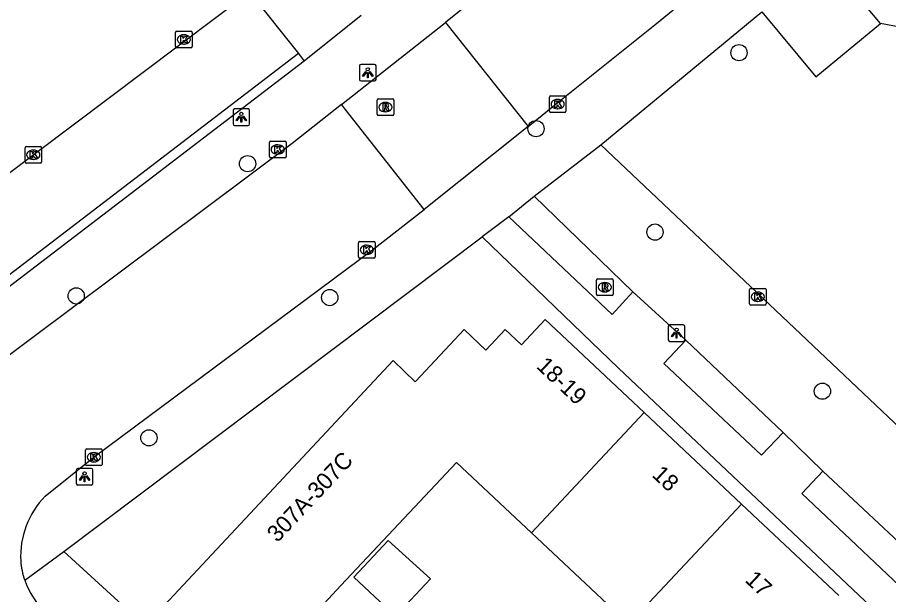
# Model space of a CAD drawing. Extents: x 159040 to 160094, y 381214 to 382518.
# Drawn here: x 159414.8 to 159467.3, y 381586.5 to 381621.3 of the extents above; entities that cross this region are included whole.
import ezdxf

# ---------------------------------------------------------------- set-up
doc = ezdxf.new("R2010")
doc.units = 0
for name, color, linetype in [('IMGEO_Boom', 7, 'Continuous'), ('IMGEO_Kolk', 7, 'Continuous'), ('IMGEO_Lichtpunt', 7, 'Continuous'), ('IMGEO_Pand', 7, 'Continuous'), ('IMGEO_Pand_nummerreeks', 7, 'Continuous'), ('IMGEO_Pand_vergunning_verleend', 7, 'Continuous'), ('IMGEO_Parkeervlak_open', 7, 'Continuous'), ('IMGEO_Rijbaan_lokaal_gesloten', 7, 'Continuous'), ('IMGEO_Rijbaan_lokaal_open', 7, 'Continuous'), ('IMGEO_Rioolput', 7, 'Continuous'), ('IMGEO_Voetpad_open', 7, 'Continuous')]:
    doc.layers.add(name, color=color, linetype=linetype)

msp = doc.modelspace()

# ---------------------------------------------------------------- linework, layer by layer
at = {"layer": 'IMGEO_Boom'}
for centre in [(159458.283, 381619.184), (159446.046, 381614.604), (159428.658, 381612.493), (159453.222, 381608.373), (159418.325, 381604.526), (159433.61, 381604.427), (159463.311, 381598.784), (159422.709, 381595.975)]:
    msp.add_circle(centre, 0.489, dxfattribs=at)
at = {"layer": 'IMGEO_Kolk'}
for p, q in [((159424.388, 381620.482), (159425.24, 381620.482)), ((159424.313, 381619.556), (159424.313, 381620.408)), ((159424.801, 381620.262), (159424.826, 381620.262)), ((159425.314, 381620.408), (159425.314, 381619.556)), ((159425.24, 381619.482), (159424.388, 381619.482)), ((159424.824, 381619.702), (159424.799, 381619.702)), ((159446.851, 381615.66), (159446.851, 381616.512)), ((159446.926, 381616.586), (159447.778, 381616.586)), ((159447.339, 381616.366), (159447.364, 381616.366)), ((159447.852, 381616.512), (159447.852, 381615.66)), ((159447.362, 381615.806), (159447.337, 381615.806)), ((159447.778, 381615.586), (159446.926, 381615.586)), ((159429.975, 381612.925), (159429.975, 381613.777)), ((159430.05, 381613.851), (159430.902, 381613.851)), ((159430.463, 381613.631), (159430.488, 381613.631)), ((159430.976, 381613.777), (159430.976, 381612.925)), ((159415.238, 381612.604), (159415.238, 381613.456)), ((159415.313, 381613.53), (159416.165, 381613.53)), ((159415.726, 381613.31), (159415.751, 381613.31)), ((159416.239, 381613.456), (159416.239, 381612.604)), ((159415.749, 381612.75), (159415.724, 381612.75)), ((159430.902, 381612.851), (159430.05, 381612.851)), ((159430.486, 381613.071), (159430.461, 381613.071)), ((159416.165, 381612.53), (159415.313, 381612.53)), ((159435.347, 381606.879), (159435.347, 381607.731)), ((159435.422, 381607.805), (159436.274, 381607.805)), ((159435.835, 381607.585), (159435.86, 381607.585)), ((159436.348, 381607.731), (159436.348, 381606.879)), ((159436.274, 381606.805), (159435.422, 381606.805)), ((159435.858, 381607.025), (159435.833, 381607.025)), ((159458.916, 381604.052), (159458.916, 381604.904)), ((159458.991, 381604.978), (159459.843, 381604.978)), ((159459.404, 381604.758), (159459.429, 381604.758)), ((159459.917, 381604.904), (159459.917, 381604.052)), ((159459.427, 381604.198), (159459.402, 381604.198)), ((159459.843, 381603.978), (159458.991, 381603.978)), ((159418.886, 381594.377), (159418.886, 381595.229)), ((159418.961, 381595.303), (159419.813, 381595.303)), ((159419.887, 381595.229), (159419.887, 381594.377)), ((159419.374, 381595.083), (159419.399, 381595.083)), ((159419.813, 381594.303), (159418.961, 381594.303)), ((159419.397, 381594.523), (159419.372, 381594.523))]:
    msp.add_line(p, q, dxfattribs=at)
for points in [[(159424.388, 381620.482), (159425.24, 381620.482)], [(159424.313, 381619.556), (159424.313, 381620.408)], [(159424.634, 381620.182), (159424.757, 381620.182), (159424.757, 381620.031), (159424.887, 381620.182), (159425.051, 381620.182), (159424.905, 381620.031), (159425.058, 381619.782), (159424.906, 381619.782), (159424.821, 381619.946), (159424.757, 381619.879), (159424.757, 381619.782), (159424.634, 381619.782), (159424.634, 381620.182)], [(159425.314, 381620.408), (159425.314, 381619.556)], [(159425.24, 381619.482), (159424.388, 381619.482)], [(159446.851, 381615.66), (159446.851, 381616.512)], [(159446.926, 381616.586), (159447.778, 381616.586)], [(159447.172, 381616.286), (159447.295, 381616.286), (159447.295, 381616.135), (159447.425, 381616.286), (159447.589, 381616.286), (159447.443, 381616.135), (159447.596, 381615.886), (159447.444, 381615.886), (159447.359, 381616.05), (159447.295, 381615.983), (159447.295, 381615.886), (159447.172, 381615.886), (159447.172, 381616.286)], [(159447.852, 381616.512), (159447.852, 381615.66)], [(159447.778, 381615.586), (159446.926, 381615.586)], [(159429.975, 381612.925), (159429.975, 381613.777)], [(159430.05, 381613.851), (159430.902, 381613.851)], [(159430.976, 381613.777), (159430.976, 381612.925)], [(159415.238, 381612.604), (159415.238, 381613.456)], [(159415.313, 381613.53), (159416.165, 381613.53)], [(159415.559, 381613.23), (159415.682, 381613.23), (159415.682, 381613.079), (159415.812, 381613.23), (159415.976, 381613.23), (159415.83, 381613.079), (159415.983, 381612.83), (159415.831, 381612.83), (159415.746, 381612.994), (159415.682, 381612.927), (159415.682, 381612.83), (159415.559, 381612.83), (159415.559, 381613.23)], [(159416.239, 381613.456), (159416.239, 381612.604)], [(159430.296, 381613.551), (159430.419, 381613.551), (159430.419, 381613.4), (159430.549, 381613.551), (159430.713, 381613.551), (159430.567, 381613.4), (159430.72, 381613.151), (159430.568, 381613.151), (159430.483, 381613.315), (159430.419, 381613.248), (159430.419, 381613.151), (159430.296, 381613.151), (159430.296, 381613.551)], [(159430.902, 381612.851), (159430.05, 381612.851)], [(159416.165, 381612.53), (159415.313, 381612.53)], [(159435.347, 381606.879), (159435.347, 381607.731)], [(159435.422, 381607.805), (159436.274, 381607.805)], [(159435.668, 381607.505), (159435.791, 381607.505), (159435.791, 381607.354), (159435.921, 381607.505), (159436.085, 381607.505), (159435.939, 381607.354), (159436.092, 381607.105), (159435.94, 381607.105), (159435.855, 381607.269), (159435.791, 381607.202), (159435.791, 381607.105), (159435.668, 381607.105), (159435.668, 381607.505)], [(159436.348, 381607.731), (159436.348, 381606.879)], [(159436.274, 381606.805), (159435.422, 381606.805)], [(159458.916, 381604.052), (159458.916, 381604.904)], [(159458.991, 381604.978), (159459.843, 381604.978)], [(159459.917, 381604.904), (159459.917, 381604.052)], [(159459.237, 381604.678), (159459.36, 381604.678), (159459.36, 381604.527), (159459.49, 381604.678), (159459.654, 381604.678), (159459.508, 381604.527), (159459.661, 381604.278), (159459.509, 381604.278), (159459.424, 381604.442), (159459.36, 381604.375), (159459.36, 381604.278), (159459.237, 381604.278), (159459.237, 381604.678)], [(159459.843, 381603.978), (159458.991, 381603.978)], [(159418.886, 381594.377), (159418.886, 381595.229)], [(159418.961, 381595.303), (159419.813, 381595.303)], [(159419.887, 381595.229), (159419.887, 381594.377)], [(159419.207, 381595.003), (159419.33, 381595.003), (159419.33, 381594.852), (159419.46, 381595.003), (159419.624, 381595.003), (159419.478, 381594.852), (159419.631, 381594.603), (159419.479, 381594.603), (159419.394, 381594.767), (159419.33, 381594.7), (159419.33, 381594.603), (159419.207, 381594.603), (159419.207, 381595.003)], [(159419.813, 381594.303), (159418.961, 381594.303)]]:
    msp.add_lwpolyline(points, dxfattribs=at)
for centre, start, end in [((159424.39, 381620.406), 91.552, 178.448), ((159424.39, 381620.406), 91.552, 178.448), ((159425.238, 381620.406), 1.552, 88.448), ((159425.238, 381620.406), 1.552, 88.448), ((159424.39, 381619.558), 181.552, 268.448), ((159424.39, 381619.558), 181.552, 268.448), ((159425.238, 381619.558), 271.552, 358.448), ((159425.238, 381619.558), 271.552, 358.448), ((159446.928, 381616.51), 91.552, 178.448), ((159446.928, 381616.51), 91.552, 178.448), ((159447.776, 381616.51), 1.552, 88.448), ((159447.776, 381616.51), 1.552, 88.448), ((159446.928, 381615.662), 181.552, 268.448), ((159446.928, 381615.662), 181.552, 268.448), ((159447.776, 381615.662), 271.552, 358.448), ((159447.776, 381615.662), 271.552, 358.448), ((159430.052, 381613.775), 91.552, 178.448), ((159430.052, 381613.775), 91.552, 178.448), ((159430.9, 381613.775), 1.552, 88.448), ((159430.9, 381613.775), 1.552, 88.448), ((159415.315, 381613.454), 91.552, 178.448), ((159415.315, 381613.454), 91.552, 178.448), ((159416.163, 381613.454), 1.552, 88.448), ((159416.163, 381613.454), 1.552, 88.448), ((159415.315, 381612.606), 181.552, 268.448), ((159415.315, 381612.606), 181.552, 268.448), ((159416.163, 381612.606), 271.552, 358.448), ((159416.163, 381612.606), 271.552, 358.448), ((159430.052, 381612.927), 181.552, 268.448), ((159430.052, 381612.927), 181.552, 268.448), ((159430.9, 381612.927), 271.552, 358.448), ((159430.9, 381612.927), 271.552, 358.448), ((159435.424, 381607.729), 91.552, 178.448), ((159435.424, 381607.729), 91.552, 178.448), ((159436.272, 381607.729), 1.552, 88.448), ((159436.272, 381607.729), 1.552, 88.448), ((159435.424, 381606.881), 181.552, 268.448), ((159435.424, 381606.881), 181.552, 268.448), ((159436.272, 381606.881), 271.552, 358.448), ((159436.272, 381606.881), 271.552, 358.448), ((159458.993, 381604.902), 91.552, 178.448), ((159458.993, 381604.902), 91.552, 178.448), ((159459.841, 381604.902), 1.552, 88.448), ((159459.841, 381604.902), 1.552, 88.448), ((159458.993, 381604.054), 181.552, 268.448), ((159458.993, 381604.054), 181.552, 268.448), ((159459.841, 381604.054), 271.552, 358.448), ((159459.841, 381604.054), 271.552, 358.448), ((159418.963, 381595.227), 91.552, 178.448), ((159418.963, 381595.227), 91.552, 178.448), ((159419.811, 381595.227), 1.552, 88.448), ((159419.811, 381595.227), 1.552, 88.448), ((159418.963, 381594.379), 181.552, 268.448), ((159418.963, 381594.379), 181.552, 268.448), ((159419.811, 381594.379), 271.552, 358.448), ((159419.811, 381594.379), 271.552, 358.448)]:
    msp.add_arc(centre, 0.0765, start, end, dxfattribs=at)
for centre, major_axis, ratio, start_param, end_param in [((159424.8, 381619.982), (-0.387, 0.002), 0.722429, 4.712389, 7.853982), ((159424.825, 381619.982), (-0.39, 0.002), 0.717154, 1.570796, 4.712389), ((159447.338, 381616.086), (-0.387, 0.002), 0.722429, 4.712389, 7.853982), ((159447.363, 381616.086), (-0.39, 0.002), 0.717154, 1.570796, 4.712389), ((159430.462, 381613.351), (-0.387, 0.002), 0.722429, 4.712389, 7.853982), ((159430.487, 381613.351), (-0.39, 0.002), 0.717154, 1.570796, 4.712389), ((159415.725, 381613.03), (-0.387, 0.002), 0.722429, 4.712389, 7.853982), ((159415.75, 381613.03), (-0.39, 0.002), 0.717154, 1.570796, 4.712389), ((159435.834, 381607.305), (-0.387, 0.002), 0.722429, 4.712389, 7.853982), ((159435.859, 381607.305), (-0.39, 0.002), 0.717154, 1.570796, 4.712389), ((159459.403, 381604.478), (-0.387, 0.002), 0.722429, 4.712389, 7.853982), ((159459.428, 381604.478), (-0.39, 0.002), 0.717154, 1.570796, 4.712389), ((159419.373, 381594.803), (-0.387, 0.002), 0.722429, 4.712389, 7.853982), ((159419.398, 381594.803), (-0.39, 0.002), 0.717154, 1.570796, 4.712389)]:
    msp.add_ellipse(centre, major_axis=major_axis, ratio=ratio, start_param=start_param, end_param=end_param, dxfattribs=at)
at = {"layer": 'IMGEO_Lichtpunt'}
for p, q in [((159435.407, 381618.383), (159435.407, 381617.576)), ((159435.407, 381618.383), (159435.407, 381617.576)), ((159436.309, 381618.478), (159435.501, 381618.478)), ((159436.309, 381618.478), (159435.501, 381618.478)), ((159436.403, 381617.576), (159436.403, 381618.383)), ((159436.403, 381617.576), (159436.403, 381618.383)), ((159435.501, 381617.482), (159436.309, 381617.482)), ((159435.501, 381617.482), (159436.309, 381617.482)), ((159428.682, 381615.791), (159427.874, 381615.791)), ((159428.682, 381615.791), (159427.874, 381615.791)), ((159427.78, 381615.696), (159427.78, 381614.889)), ((159427.78, 381615.696), (159427.78, 381614.889)), ((159428.776, 381614.889), (159428.776, 381615.696)), ((159428.776, 381614.889), (159428.776, 381615.696)), ((159427.874, 381614.795), (159428.682, 381614.795)), ((159427.874, 381614.795), (159428.682, 381614.795)), ((159454.021, 381602.687), (159454.021, 381601.88)), ((159454.021, 381602.687), (159454.021, 381601.88)), ((159454.923, 381602.782), (159454.115, 381602.782)), ((159454.923, 381602.782), (159454.115, 381602.782)), ((159455.017, 381601.88), (159455.017, 381602.687)), ((159455.017, 381601.88), (159455.017, 381602.687)), ((159454.115, 381601.786), (159454.923, 381601.786)), ((159454.115, 381601.786), (159454.923, 381601.786)), ((159418.331, 381594.034), (159418.331, 381593.227)), ((159418.331, 381594.034), (159418.331, 381593.227)), ((159419.233, 381594.129), (159418.425, 381594.129)), ((159419.233, 381594.129), (159418.425, 381594.129)), ((159419.327, 381593.227), (159419.327, 381594.034)), ((159419.327, 381593.227), (159419.327, 381594.034)), ((159418.425, 381593.133), (159419.233, 381593.133)), ((159418.425, 381593.133), (159419.233, 381593.133))]:
    msp.add_line(p, q, dxfattribs=at)
for points in [[(159435.781, 381618.047), (159435.82, 381618.019), (159435.632, 381617.757), (159435.594, 381617.784), (159435.781, 381618.047)], [(159435.883, 381617.999), (159435.93, 381617.999), (159435.93, 381617.677), (159435.883, 381617.677), (159435.883, 381617.999)], [(159435.993, 381618.019), (159436.031, 381618.046), (159436.218, 381617.784), (159436.179, 381617.756), (159435.993, 381618.019)], [(159428.154, 381615.36), (159428.193, 381615.332), (159428.005, 381615.07), (159427.967, 381615.097), (159428.154, 381615.36)], [(159428.256, 381615.312), (159428.303, 381615.312), (159428.303, 381614.99), (159428.256, 381614.99), (159428.256, 381615.312)], [(159428.366, 381615.332), (159428.404, 381615.359), (159428.591, 381615.097), (159428.552, 381615.069), (159428.366, 381615.332)], [(159454.395, 381602.351), (159454.434, 381602.323), (159454.246, 381602.061), (159454.208, 381602.088), (159454.395, 381602.351)], [(159454.497, 381602.303), (159454.544, 381602.303), (159454.544, 381601.981), (159454.497, 381601.981), (159454.497, 381602.303)], [(159454.607, 381602.323), (159454.645, 381602.35), (159454.832, 381602.088), (159454.793, 381602.06), (159454.607, 381602.323)], [(159418.705, 381593.698), (159418.744, 381593.67), (159418.556, 381593.408), (159418.518, 381593.435), (159418.705, 381593.698)], [(159418.917, 381593.67), (159418.955, 381593.697), (159419.142, 381593.435), (159419.103, 381593.407), (159418.917, 381593.67)], [(159418.807, 381593.65), (159418.854, 381593.65), (159418.854, 381593.328), (159418.807, 381593.328), (159418.807, 381593.65)]]:
    msp.add_lwpolyline(points, dxfattribs=at)
for centre in [(159435.906, 381618.181), (159428.279, 381615.494), (159454.52, 381602.485), (159418.83, 381593.832)]:
    msp.add_circle(centre, 0.0994, dxfattribs=at)
for centre, start, end in [((159435.501, 381618.383), 90, 180), ((159435.501, 381618.383), 90, 180), ((159436.309, 381618.383), 0, 90), ((159436.309, 381618.383), 0, 90), ((159435.501, 381617.576), 180, 270), ((159435.501, 381617.576), 180, 270), ((159436.309, 381617.576), 270, 0), ((159436.309, 381617.576), 270, 360), ((159427.874, 381615.696), 90, 180), ((159427.874, 381615.696), 90, 180), ((159428.682, 381615.696), 0, 90), ((159428.682, 381615.696), 0, 90), ((159427.874, 381614.889), 180, 270), ((159427.874, 381614.889), 180, 270), ((159428.682, 381614.889), 270, 0), ((159428.682, 381614.889), 270, 360), ((159454.115, 381602.687), 90, 180), ((159454.115, 381602.687), 90, 180), ((159454.923, 381602.687), 0, 90), ((159454.923, 381602.687), 0, 90), ((159454.115, 381601.88), 180, 270), ((159454.115, 381601.88), 180, 270), ((159454.923, 381601.88), 270, 0), ((159454.923, 381601.88), 270, 360), ((159418.425, 381594.034), 90, 180), ((159418.425, 381594.034), 90, 180), ((159419.233, 381594.034), 0, 90), ((159419.233, 381594.034), 0, 90), ((159418.425, 381593.227), 180, 270), ((159418.425, 381593.227), 180, 270), ((159419.233, 381593.227), 270, 0), ((159419.233, 381593.227), 270, 360)]:
    msp.add_arc(centre, 0.0946, start, end, dxfattribs=at)
at = {"layer": 'IMGEO_Pand'}
for points in [[(159422.487, 381584.653), (159437.43, 381600.625), (159438.757, 381599.344), (159438.795, 381599.385), (159441.715, 381602.495), (159443.023, 381601.267), (159444.183, 381602.502), (159445.162, 381601.583), (159446.596, 381603.11), (159452.574, 381597.495)], [(159452.574, 381597.495), (159445.774, 381590.255)], [(159458.441, 381591.985), (159452.574, 381597.495)], [(159445.774, 381590.255), (159441.258, 381594.496), (159434.282, 381587.068), (159432.769, 381585.457), (159437.359, 381581.156)], [(159451.64, 381584.745), (159458.441, 381591.985)], [(159464.308, 381586.475), (159458.441, 381591.985)], [(159451.64, 381584.745), (159445.774, 381590.255)]]:
    msp.add_lwpolyline(points, dxfattribs=at)
at = {"layer": 'IMGEO_Pand_vergunning_verleend'}
msp.add_lwpolyline([(159437.141, 381589.797), (159439.677, 381587.479), (159437.578, 381585.235), (159435.069, 381587.582), (159437.141, 381589.797)], dxfattribs=at)
at = {"layer": 'IMGEO_Parkeervlak_open'}
for points in [[(159466.819, 381620.932), (159463.542, 381624.857)], [(159431.736, 381619.126), (159408.796, 381601.598)], [(159451.892, 381604.781), (159445.932, 381610.544)], [(159460.937, 381596.304), (159455.077, 381601.853)], [(159470.365, 381587.393), (159463.335, 381593.97)]]:
    msp.add_lwpolyline(points, dxfattribs=at)
at = {"layer": 'IMGEO_Rijbaan_lokaal_gesloten'}
for points in [[(159459.028, 381636.066), (159450.889, 381629.337), (159448.16, 381627.105), (159446.76, 381625.959), (159440.585, 381621.001)], [(159445.569, 381614.728), (159447.581, 381616.353), (159453.215, 381620.871), (159456.567, 381623.617), (159463.852, 381629.598)], [(159434.322, 381616.063), (159431.341, 381613.713), (159412.969, 381600.002), (159408.536, 381596.375)], [(159416.449, 381592.464), (159419.409, 381594.821), (159436.181, 381607.304), (159439.305, 381609.73)]]:
    msp.add_lwpolyline(points, dxfattribs=at)
for centre, radius, start, end in [((159420.187, 381588.826), 5.216, 135.7806, 182.9273), ((159419.64, 381588.926), 4.676, 184.4886, 199.0599), ((159419.638, 381588.92), 4.672, 198.9924, 228.1717)]:
    msp.add_arc(centre, radius, start, end, dxfattribs=at)
at = {"layer": 'IMGEO_Rijbaan_lokaal_open'}
for points in [[(159449.954, 381613.64), (159459.65, 381621.646)], [(159459.65, 381621.646), (159462.913, 381617.737), (159466.819, 381620.932)], [(159434.322, 381616.063), (159440.585, 381621.001)], [(159440.585, 381621.001), (159445.569, 381614.728)], [(159469.771, 381620.37), (159466.819, 381620.932)], [(159439.305, 381609.73), (159434.322, 381616.063)], [(159445.569, 381614.728), (159439.305, 381609.73)], [(159494.772, 381571.228), (159449.954, 381613.64)]]:
    msp.add_lwpolyline(points, dxfattribs=at)
at = {"layer": 'IMGEO_Rioolput'}
for p, q in [((159436.468, 381615.48), (159436.468, 381616.332)), ((159436.543, 381616.406), (159437.395, 381616.406)), ((159437.469, 381616.332), (159437.469, 381615.48)), ((159436.956, 381616.186), (159436.981, 381616.186)), ((159437.395, 381615.406), (159436.543, 381615.406)), ((159436.979, 381615.626), (159436.954, 381615.626)), ((159449.693, 381604.626), (159449.693, 381605.478)), ((159449.768, 381605.552), (159450.62, 381605.552)), ((159450.181, 381605.332), (159450.206, 381605.332)), ((159450.694, 381605.478), (159450.694, 381604.626)), ((159450.204, 381604.772), (159450.179, 381604.772)), ((159450.62, 381604.552), (159449.768, 381604.552))]:
    msp.add_line(p, q, dxfattribs=at)
for points in [[(159436.468, 381615.48), (159436.468, 381616.332)], [(159436.543, 381616.406), (159437.395, 381616.406)], [(159437.469, 381616.332), (159437.469, 381615.48)], [(159437.057, 381616.104), (159436.805, 381616.106), (159436.805, 381615.706)], [(159436.805, 381615.706), (159436.929, 381615.706), (159436.929, 381615.868), (159436.94, 381615.868)], [(159436.983, 381616.025), (159436.929, 381616.025), (159436.929, 381615.944)], [(159436.929, 381615.944), (159436.981, 381615.944)], [(159436.987, 381615.839), (159437.058, 381615.706), (159437.198, 381615.706), (159437.133, 381615.832)], [(159437.395, 381615.406), (159436.543, 381615.406)], [(159449.693, 381604.626), (159449.693, 381605.478)], [(159449.768, 381605.552), (159450.62, 381605.552)], [(159450.282, 381605.25), (159450.03, 381605.252), (159450.03, 381604.852)], [(159450.694, 381605.478), (159450.694, 381604.626)], [(159450.03, 381604.852), (159450.154, 381604.852), (159450.154, 381605.014), (159450.165, 381605.014)], [(159450.208, 381605.171), (159450.154, 381605.171), (159450.154, 381605.09)], [(159450.154, 381605.09), (159450.206, 381605.09)], [(159450.212, 381604.985), (159450.283, 381604.852), (159450.423, 381604.852), (159450.358, 381604.978)], [(159450.62, 381604.552), (159449.768, 381604.552)]]:
    msp.add_lwpolyline(points, dxfattribs=at)
for centre, radius, start, end in [((159436.545, 381616.33), 0.0765, 91.552, 178.448), ((159436.545, 381616.33), 0.0765, 91.552, 178.448), ((159437.393, 381616.33), 0.0765, 1.552, 88.448), ((159437.393, 381616.33), 0.0765, 1.552, 88.448), ((159436.939, 381615.815), 0.0533, 26.0293, 88.6989), ((159436.965, 381616.133), 0.19, 274.7715, 282.9687), ((159436.989, 381615.929), 0.0964, 77.0061, 93.1865), ((159437.003, 381615.986), 0.0378, 276.6634, 79.6772), ((159437.056, 381615.994), 0.109, 350.3612, 89.416), ((159437.054, 381615.994), 0.112, 277.5842, 350.9817), ((159437.038, 381615.779), 0.108, 29.5134, 73.7905), ((159436.545, 381615.482), 0.0765, 181.552, 268.448), ((159436.545, 381615.482), 0.0765, 181.552, 268.448), ((159437.393, 381615.482), 0.0765, 271.552, 358.448), ((159437.393, 381615.482), 0.0765, 271.552, 358.448), ((159449.77, 381605.476), 0.0765, 91.552, 178.448), ((159449.77, 381605.476), 0.0765, 91.552, 178.448), ((159450.281, 381605.14), 0.109, 350.3612, 89.416), ((159450.618, 381605.476), 0.0765, 1.552, 88.448), ((159450.618, 381605.476), 0.0765, 1.552, 88.448), ((159450.164, 381604.961), 0.0533, 26.0293, 88.6989), ((159450.19, 381605.279), 0.19, 274.7715, 282.9687), ((159450.214, 381605.075), 0.0964, 77.0061, 93.1865), ((159450.228, 381605.132), 0.0378, 276.6634, 79.6772), ((159450.279, 381605.14), 0.112, 277.5842, 350.9817), ((159450.263, 381604.925), 0.108, 29.5134, 73.7905), ((159449.77, 381604.628), 0.0765, 181.552, 268.448), ((159449.77, 381604.628), 0.0765, 181.552, 268.448), ((159450.618, 381604.628), 0.0765, 271.552, 358.448), ((159450.618, 381604.628), 0.0765, 271.552, 358.448)]:
    msp.add_arc(centre, radius, start, end, dxfattribs=at)
for centre, major_axis, ratio, start_param, end_param in [((159436.955, 381615.906), (-0.387, 0.002), 0.722429, 4.712389, 7.853982), ((159436.98, 381615.906), (-0.39, 0.002), 0.717154, 1.570796, 4.712389), ((159450.18, 381605.052), (-0.387, 0.002), 0.722429, 4.712389, 7.853982), ((159450.205, 381605.052), (-0.39, 0.002), 0.717154, 1.570796, 4.712389)]:
    msp.add_ellipse(centre, major_axis=major_axis, ratio=ratio, start_param=start_param, end_param=end_param, dxfattribs=at)
at = {"layer": 'IMGEO_Voetpad_open'}
for points in [[(159403.188, 381603.6), (159428.778, 381622.85), (159431.736, 381619.126)], [(159435.51, 381621.424), (159432.061, 381618.681)], [(159431.736, 381619.126), (159432.061, 381618.681)], [(159432.061, 381618.681), (159409.141, 381601.163), (159408.665, 381600.799)], [(159445.932, 381610.544), (159449.954, 381613.64)], [(159444.406, 381609.292), (159445.932, 381610.544)], [(159444.406, 381609.292), (159442.807, 381608.091)], [(159451.892, 381604.781), (159450.64, 381603.4), (159444.406, 381609.292)], [(159417.572, 381589.129), (159442.807, 381608.091)], [(159442.807, 381608.091), (159451.02, 381600.164), (159492.689, 381560.816), (159494.82, 381558.774)], [(159455.077, 381601.853), (159451.892, 381604.781)], [(159460.937, 381596.304), (159459.639, 381594.939), (159453.756, 381600.464), (159455.077, 381601.853)], [(159463.335, 381593.97), (159460.937, 381596.304)], [(159470.365, 381587.393), (159469.037, 381586.026), (159462.071, 381592.617), (159463.335, 381593.97)], [(159415.22, 381587.399), (159417.572, 381589.129)], [(159417.572, 381589.129), (159422.487, 381584.653)]]:
    msp.add_lwpolyline(points, dxfattribs=at)

# ---------------------------------------------------------------- texts
at = {"layer": 'IMGEO_Pand_nummerreeks'}
for s, rotation, p in [('18-19', 316.7933, (159446.015, 381600.226)), ('307A-307C', 46.7935, (159430.455, 381589.623)), ('18', 316.799, (159452.983, 381593.681)), ('17', 316.7949, (159458.593, 381587.342))]:
    msp.add_text(s, height=1, rotation=rotation, dxfattribs=at).set_placement(p)

doc.saveas('drawing.dxf')
